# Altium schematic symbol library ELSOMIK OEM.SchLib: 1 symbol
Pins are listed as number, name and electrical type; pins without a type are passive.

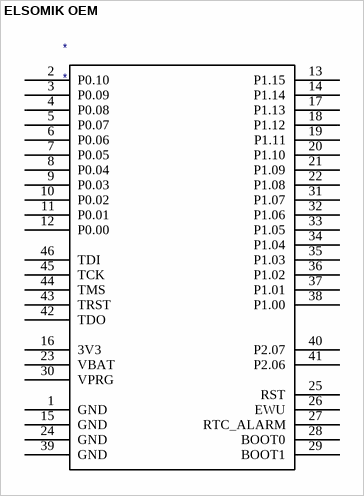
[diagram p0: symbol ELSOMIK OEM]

## ELSOMIK OEM
designator *
Модуль SOM (System on module) с микроконтроллером 1-го уровня MIK32 АМУР (к1948вк018) - ELSOMIK OEM
pins: 1 GND, 2 P0.10, 3 P0.09, 4 P0.08, 5 P0.07, 6 P0.06, 7 P0.05, 8 P0.04, 9 P0.03, 10 P0.02, 11 P0.01, 12 P0.00, 13 P1.15, 14 P1.14, 15 GND, 16 3V3, 17 P1.13, 18 P1.12, 19 P1.11, 20 P1.10, 21 P1.09, 22 P1.08, 23 VBAT, 24 GND, 25 RST, 26 EWU, 27 RTC_ALARM, 28 BOOT0, 29 BOOT1, 30 VPRG, 31 P1.07, 32 P1.06, 33 P1.05, 34 P1.04, 35 P1.03, 36 P1.02, 37 P1.01, 38 P1.00, 39 GND, 40 P2.07, 41 P2.06, 42 TDO, 43 TRST, 44 TMS, 45 TCK, 46 TDI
